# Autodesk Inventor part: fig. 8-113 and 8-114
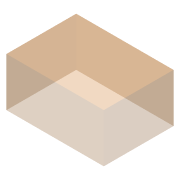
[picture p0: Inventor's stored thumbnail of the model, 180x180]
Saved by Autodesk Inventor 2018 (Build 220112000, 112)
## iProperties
Created: 2013-07
Part Number: fig. 8-113 and 8-114
Material: Generic
Document SubType Name: Modeling
Designer: CADCIM
Density: 1 g/cm^3
Appearance: Default
Author: CADCIM
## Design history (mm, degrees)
sketch "Sketch1"
  geometry: L1 (-10, 7.167)-(10, 7.167); L2 (10, 7.167)-(10, -7.167); L3 (10, -7.167)-(-10, -7.167); L4 (-10, -7.167)-(-10, 7.167); L5 (-10, 7.167)-(10, -7.167); L6 (10, 7.167)-(-10, -7.167); 1 further point
  constraints: 12 end point, 2 midpoint, 2 parallel, 1 horizontal, 1 perpendicular
  dimensions: "d0" = 20 distance of L2.end L3.end
extrude_surface "ExtrusionSrf1" sketch "Sketch1" dims "d1" = 10, "d2" = 0
patch "Boundary Patch1" dims "d3" = 5, "d4" = 0
body "Srf1"
body "Srf2"
